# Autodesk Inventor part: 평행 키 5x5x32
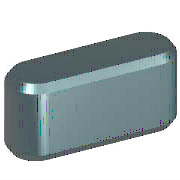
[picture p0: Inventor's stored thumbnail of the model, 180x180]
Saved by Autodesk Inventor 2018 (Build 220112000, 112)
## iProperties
Created: 2012-02
Part Number: 평행 키 5x5x32
Material: 강철, 연강
Description: 평행 키
Document SubType Name: Modeling
Standard: JIS B 1301
Designer: mdu-01
Standards Organization: JIS
Language: ko-KR
Size Designation: 5x5x32
Categories: <MemberInstance><Categories><Category DisplayName="샤프트 부품" InternalName="7f7aeb1f-a693-4053-b835-cee3144e0d98" Mnemonic="SHFT"><Category DisplayName="키" Interna
Density: 1 g/cm^3
Appearance: 기본값(2)
IsCustomPart: 1
Author: mdu-01
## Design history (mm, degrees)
workplane "Work Plane1"
workplane "Work Plane2"
sketch "스케치1"
  geometry: L1 (2.5, 2.5)-(29.5, 2.5); L2 (29.5, -2.5)-(2.5, -2.5); L3 (0, 9.4)-(0, -7.4) reference; L4 (-5, 0)-(30, 0) reference; L5 (32, 0)-(32, 7); A1 r 2.5 centre (2.5, 0) between (2.5, 2.5) and (2.5, -2.5); A2 r 2.5 centre (29.5, 0) between (29.5, -2.5) and (29.5, 2.5)
  constraints: 6 end point, 5 point on circle, 4 tangent, 3 point on line, 2 centre point, 1 horizontal, 1 parallel, 1 perpendicular
  dimensions: "d0" = 2.5 radius of A1 (= 0.5 x PB); "d13" = 2.5 radius of A2 (= 0.5 x PB); "d14" = 32 distance between parallel lines of L5 L3 (= NLG)
extrude "본체1" new body sketch "스케치1" taper "d3" = 0 deg; stored distance "d4" = 10
workplane "Work Plane3"
body "Solid1"
chamfer "모따기1" distance "d8" = 0.4 (= PHH); stored, may be unused: second distance "d9" = 0.4 (= PHH), angle "d15" = 45 deg
other parameters: "d1" = -3 (= -PNT), "d2" = 2 (= PH - PNT), "NLG" = 32 [user parameter; used in 3 equation terms], "PB" = 5 [user parameter; used in 2 equation terms], "PNT" = 3 [user parameter; used in 2 equation terms], "PH" = 5 [user parameter; used in 1 equation term], "PHH" = 0.4 [user parameter; used in 2 equation terms], "d10" = 0, "d16" = 0, "d17" = 0, "d18" = 0, "WDMIN" = 12 [user parameter], "PLB2" = 32 (= NLG) [user parameter], "WDMAX" = 17 [user parameter], "PLB1" = 32 (= NLG) [user parameter], "RR" = 0.16 [user parameter], "PUEB" = 2.3 [user parameter]
